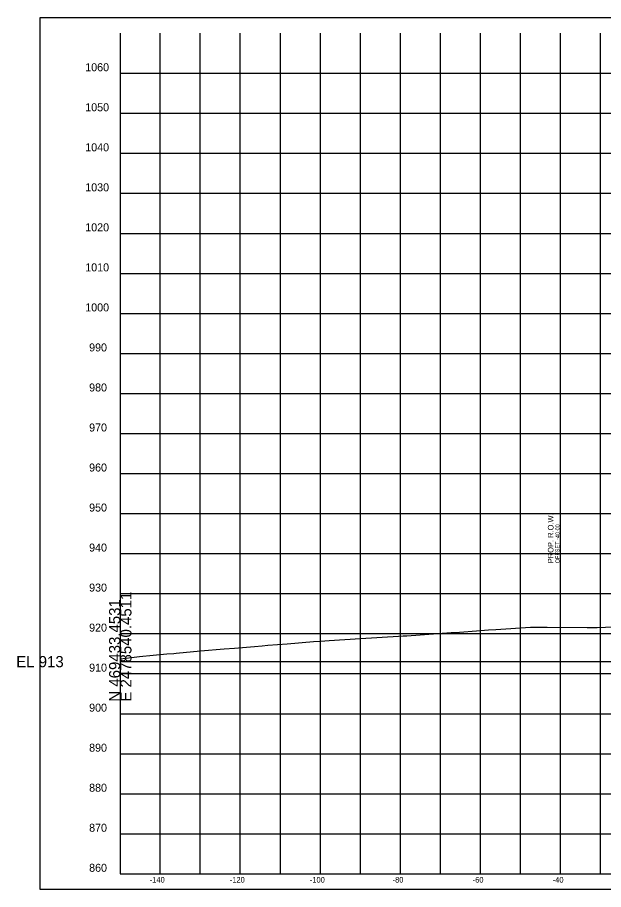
# Model space of a CAD drawing. Extents: x -26 to 2478923, y -10 to 469990.
# Drawn here: x -25.7 to 120.8, y 8443.1 to 8660.9 of the extents above; entities that cross this region are included whole.
import ezdxf

# ---------------------------------------------------------------- set-up
doc = ezdxf.new("R2010")
doc.units = 0
for name, color, linetype in [('DESIGN - ROW - Right-of-Way and Easement Labels', 7, 'Continuous'), ('DESIGN - ROW - Right-of-Way Linework', 7, 'Continuous'), ('DESIGN - SHEET - Corner Text', 7, 'Continuous'), ('DESIGN - SHEET - Light Grid', 7, 'Continuous'), ('DESIGN - SHEET - Linework', 7, 'Continuous'), ('DESIGN - SHEET - Plot Shape', 7, 'Continuous'), ('SURVEY - GROUND - Top of Ground', 7, 'Continuous')]:
    doc.layers.add(name, color=color, linetype=linetype)

msp = doc.modelspace()

# ---------------------------------------------------------------- linework, layer by layer
at = {"layer": 'DESIGN - ROW - Right-of-Way Linework'}
msp.add_line((110, 8508.57), (110, 8540.57), dxfattribs=at)
at = {"layer": 'DESIGN - SHEET - Light Grid'}
msp.add_line((0, 8500), (150, 8500), dxfattribs=at)
at = {"layer": 'DESIGN - SHEET - Linework'}
for p, q in [((10, 8447), (10, 8657)), ((10, 8447), (10, 8657)), ((10, 8447), (10, 8657)), ((10, 8447), (10, 8657)), ((20, 8447), (20, 8657)), ((20, 8447), (20, 8657)), ((20, 8447), (20, 8657)), ((20, 8447), (20, 8657)), ((30, 8447), (30, 8657)), ((30, 8447), (30, 8657)), ((30, 8447), (30, 8657)), ((30, 8447), (30, 8657)), ((40, 8447), (40, 8657)), ((40, 8447), (40, 8657)), ((40, 8447), (40, 8657)), ((40, 8447), (40, 8657)), ((50, 8447), (50, 8657)), ((50, 8447), (50, 8657)), ((50, 8447), (50, 8657)), ((50, 8447), (50, 8657)), ((60, 8447), (60, 8657)), ((60, 8447), (60, 8657)), ((60, 8447), (60, 8657)), ((60, 8447), (60, 8657)), ((70, 8447), (70, 8657)), ((70, 8447), (70, 8657)), ((70, 8447), (70, 8657)), ((70, 8447), (70, 8657)), ((80, 8447), (80, 8657)), ((80, 8447), (80, 8657)), ((80, 8447), (80, 8657)), ((80, 8447), (80, 8657)), ((90, 8447), (90, 8657)), ((90, 8447), (90, 8657)), ((90, 8447), (90, 8657)), ((90, 8447), (90, 8657)), ((100, 8447), (100, 8657)), ((100, 8447), (100, 8657)), ((100, 8447), (100, 8657)), ((100, 8447), (100, 8657)), ((110, 8447), (110, 8657)), ((110, 8447), (110, 8657)), ((110, 8447), (110, 8657)), ((110, 8447), (110, 8657)), ((120, 8447), (120, 8657)), ((120, 8447), (120, 8657)), ((120, 8447), (120, 8657)), ((120, 8447), (120, 8657)), ((0, 8647), (300, 8647)), ((0, 8647), (300, 8647)), ((0, 8647), (300, 8647)), ((0, 8647), (300, 8647)), ((0, 8637), (300, 8637)), ((0, 8637), (300, 8637)), ((0, 8637), (300, 8637)), ((0, 8637), (300, 8637)), ((0, 8627), (300, 8627)), ((0, 8627), (300, 8627)), ((0, 8627), (300, 8627)), ((0, 8627), (300, 8627)), ((0, 8617), (300, 8617)), ((0, 8617), (300, 8617)), ((0, 8617), (300, 8617)), ((0, 8617), (300, 8617)), ((0, 8607), (300, 8607)), ((0, 8607), (300, 8607)), ((0, 8607), (300, 8607)), ((0, 8607), (300, 8607)), ((0, 8597), (300, 8597)), ((0, 8597), (300, 8597)), ((0, 8597), (300, 8597)), ((0, 8597), (300, 8597)), ((0, 8587), (300, 8587)), ((0, 8587), (300, 8587)), ((0, 8587), (300, 8587)), ((0, 8587), (300, 8587)), ((0, 8577), (300, 8577)), ((0, 8577), (300, 8577)), ((0, 8577), (300, 8577)), ((0, 8577), (300, 8577)), ((0, 8567), (300, 8567)), ((0, 8567), (300, 8567)), ((0, 8567), (300, 8567)), ((0, 8567), (300, 8567)), ((0, 8557), (300, 8557)), ((0, 8557), (300, 8557)), ((0, 8557), (300, 8557)), ((0, 8557), (300, 8557)), ((0, 8547), (300, 8547)), ((0, 8547), (300, 8547)), ((0, 8547), (300, 8547)), ((0, 8547), (300, 8547)), ((0, 8537), (300, 8537)), ((0, 8537), (300, 8537)), ((0, 8537), (300, 8537)), ((0, 8537), (300, 8537)), ((0, 8527), (300, 8527)), ((0, 8527), (300, 8527)), ((0, 8527), (300, 8527)), ((0, 8527), (300, 8527)), ((0, 8517), (300, 8517)), ((0, 8517), (300, 8517)), ((0, 8517), (300, 8517)), ((0, 8517), (300, 8517)), ((0, 8507), (300, 8507)), ((0, 8507), (300, 8507)), ((0, 8507), (300, 8507)), ((0, 8507), (300, 8507)), ((0, 8497), (300, 8497)), ((0, 8497), (300, 8497)), ((0, 8497), (300, 8497)), ((0, 8497), (300, 8497)), ((0, 8487), (300, 8487)), ((0, 8487), (300, 8487)), ((0, 8487), (300, 8487)), ((0, 8487), (300, 8487)), ((0, 8477), (300, 8477)), ((0, 8477), (300, 8477)), ((0, 8477), (300, 8477)), ((0, 8477), (300, 8477)), ((0, 8467), (300, 8467)), ((0, 8467), (300, 8467)), ((0, 8467), (300, 8467)), ((0, 8467), (300, 8467)), ((0, 8457), (300, 8457)), ((0, 8457), (300, 8457)), ((0, 8457), (300, 8457)), ((0, 8457), (300, 8457))]:
    msp.add_line(p, q, dxfattribs=at)
msp.add_lwpolyline([(0, 8657), (0, 8447), (300, 8447), (300, 8657)], dxfattribs=at)
msp.add_lwpolyline([(0, 8657), (0, 8447), (300, 8447), (300, 8657)], dxfattribs=at)
msp.add_lwpolyline([(0, 8657), (0, 8447), (300, 8447), (300, 8657)], dxfattribs=at)
msp.add_lwpolyline([(0, 8657), (0, 8447), (300, 8447), (300, 8657)], dxfattribs=at)
at = {"layer": 'DESIGN - SHEET - Plot Shape'}
msp.add_lwpolyline([(-20, 8660.94), (320, 8660.94), (320, 8443.06), (-20, 8443.06)], close=True, dxfattribs=at)
msp.add_lwpolyline([(-20, 8660.94), (320, 8660.94), (320, 8443.06), (-20, 8443.06)], close=True, dxfattribs=at)
msp.add_lwpolyline([(-20, 8660.94), (320, 8660.94), (320, 8443.06), (-20, 8443.06)], close=True, dxfattribs=at)
msp.add_lwpolyline([(-20, 8660.94), (320, 8660.94), (320, 8443.06), (-20, 8443.06)], close=True, dxfattribs=at)
at = {"layer": 'SURVEY - GROUND - Top of Ground'}
msp.add_lwpolyline([(0, 8500.73), (2.85, 8501.07), (4.84, 8501.29), (11.67, 8501.92), (13.35, 8502.07), (14, 8502.14), (20.01, 8502.68), (25.96, 8503.17), (28.52, 8503.37), (33.53, 8503.79), (35.43, 8503.97), (36.88, 8504.08), (41.7, 8504.42), (48.32, 8505.04), (50.03, 8505.15), (52.23, 8505.29), (60.06, 8505.8), (69.55, 8506.36), (70.66, 8506.43), (71.59, 8506.48), (82.67, 8507.28), (84.74, 8507.4), (89.03, 8507.72), (92.02, 8507.95), (93.85, 8508.05), (102.52, 8508.6), (106.67, 8508.6), (116.67, 8508.5), (117.79, 8508.49), (119.21, 8508.54), (127.48, 8508.86)], dxfattribs=at)

# ---------------------------------------------------------------- texts
at = {"layer": 'DESIGN - ROW - Right-of-Way and Easement Labels'}
for s, height, p in [('PROP. R.O.W.', 1.4, (108.25, 8524.57)), ('OFFSET -40.00', 1, (109.75, 8524.57))]:
    msp.add_text(s, height=height, rotation=90, dxfattribs=at).set_placement(p)
at = {"layer": 'DESIGN - SHEET - Corner Text'}
for s, height, p in [('1060', 2, (-8.75, 8647.5)), ('1060', 2, (-8.75, 8647.5)), ('1060', 2, (-8.75, 8647.5)), ('1060', 2, (-8.75, 8647.5)), ('1050', 2, (-8.75, 8637.5)), ('1050', 2, (-8.75, 8637.5)), ('1050', 2, (-8.75, 8637.5)), ('1050', 2, (-8.75, 8637.5)), ('1040', 2, (-8.75, 8627.5)), ('1040', 2, (-8.75, 8627.5)), ('1040', 2, (-8.75, 8627.5)), ('1040', 2, (-8.75, 8627.5)), ('1030', 2, (-8.75, 8617.5)), ('1030', 2, (-8.75, 8617.5)), ('1030', 2, (-8.75, 8617.5)), ('1030', 2, (-8.75, 8617.5)), ('1020', 2, (-8.75, 8607.5)), ('1020', 2, (-8.75, 8607.5)), ('1020', 2, (-8.75, 8607.5)), ('1020', 2, (-8.75, 8607.5)), ('1010', 2, (-8.75, 8597.5)), ('1010', 2, (-8.75, 8597.5)), ('1010', 2, (-8.75, 8597.5)), ('1010', 2, (-8.75, 8597.5)), ('1000', 2, (-8.75, 8587.5)), ('1000', 2, (-8.75, 8587.5)), ('1000', 2, (-8.75, 8587.5)), ('1000', 2, (-8.75, 8587.5)), ('990', 2, (-7.78, 8577.5)), ('990', 2, (-7.78, 8577.5)), ('990', 2, (-7.78, 8577.5)), ('990', 2, (-7.78, 8577.5)), ('980', 2, (-7.78, 8567.5)), ('980', 2, (-7.78, 8567.5)), ('980', 2, (-7.78, 8567.5)), ('980', 2, (-7.78, 8567.5)), ('970', 2, (-7.78, 8557.5)), ('970', 2, (-7.78, 8557.5)), ('970', 2, (-7.78, 8557.5)), ('970', 2, (-7.78, 8557.5)), ('960', 2, (-7.78, 8547.5)), ('960', 2, (-7.78, 8547.5)), ('960', 2, (-7.78, 8547.5)), ('960', 2, (-7.78, 8547.5)), ('950', 2, (-7.78, 8537.5)), ('950', 2, (-7.78, 8537.5)), ('950', 2, (-7.78, 8537.5)), ('950', 2, (-7.78, 8537.5)), ('940', 2, (-7.78, 8527.5)), ('940', 2, (-7.78, 8527.5)), ('940', 2, (-7.78, 8527.5)), ('940', 2, (-7.78, 8527.5)), ('930', 2, (-7.78, 8517.5)), ('930', 2, (-7.78, 8517.5)), ('930', 2, (-7.78, 8517.5)), ('930', 2, (-7.78, 8517.5)), ('920', 2, (-7.78, 8507.5)), ('920', 2, (-7.78, 8507.5)), ('920', 2, (-7.78, 8507.5)), ('920', 2, (-7.78, 8507.5)), ('910', 2, (-7.78, 8497.5)), ('910', 2, (-7.78, 8497.5)), ('910', 2, (-7.78, 8497.5)), ('910', 2, (-7.78, 8497.5)), ('900', 2, (-7.78, 8487.5)), ('900', 2, (-7.78, 8487.5)), ('900', 2, (-7.78, 8487.5)), ('900', 2, (-7.78, 8487.5)), ('890', 2, (-7.78, 8477.5)), ('890', 2, (-7.78, 8477.5)), ('890', 2, (-7.78, 8477.5)), ('890', 2, (-7.78, 8477.5)), ('880', 2, (-7.78, 8467.5)), ('880', 2, (-7.78, 8467.5)), ('880', 2, (-7.78, 8467.5)), ('880', 2, (-7.78, 8467.5)), ('870', 2, (-7.78, 8457.5)), ('870', 2, (-7.78, 8457.5)), ('870', 2, (-7.78, 8457.5)), ('870', 2, (-7.78, 8457.5)), ('860', 2, (-7.78, 8447.5)), ('860', 2, (-7.78, 8447.5)), ('860', 2, (-7.78, 8447.5)), ('860', 2, (-7.78, 8447.5)), ('-140', 1.4, (7.37, 8444.8)), ('-140', 1.4, (7.37, 8444.8)), ('-140', 1.4, (7.37, 8444.8)), ('-140', 1.4, (7.37, 8444.8)), ('-120', 1.4, (27.37, 8444.8)), ('-120', 1.4, (27.37, 8444.8)), ('-120', 1.4, (27.37, 8444.8)), ('-120', 1.4, (27.37, 8444.8)), ('-100', 1.4, (47.37, 8444.8)), ('-100', 1.4, (47.37, 8444.8)), ('-100', 1.4, (47.37, 8444.8)), ('-100', 1.4, (47.37, 8444.8)), ('-80', 1.4, (68.06, 8444.8)), ('-80', 1.4, (68.06, 8444.8)), ('-80', 1.4, (68.06, 8444.8)), ('-80', 1.4, (68.06, 8444.8)), ('-60', 1.4, (88.06, 8444.8)), ('-60', 1.4, (88.06, 8444.8)), ('-60', 1.4, (88.06, 8444.8)), ('-60', 1.4, (88.06, 8444.8)), ('-40', 1.4, (108.06, 8444.8)), ('-40', 1.4, (108.06, 8444.8)), ('-40', 1.4, (108.06, 8444.8)), ('-40', 1.4, (108.06, 8444.8))]:
    msp.add_text(s, height=height, dxfattribs=at).set_placement(p)
at = {"layer": 'DESIGN - SHEET - Light Grid'}
for s, p in [('E 2478540.4511', (2.8, 8490)), ('N 469433.4531', (0, 8490))]:
    msp.add_text(s, height=2.8, rotation=90, dxfattribs=at).set_placement(p)
msp.add_text('EL 913', height=2.8, dxfattribs=at).set_placement((-26, 8498.6))

doc.saveas('drawing.dxf')
